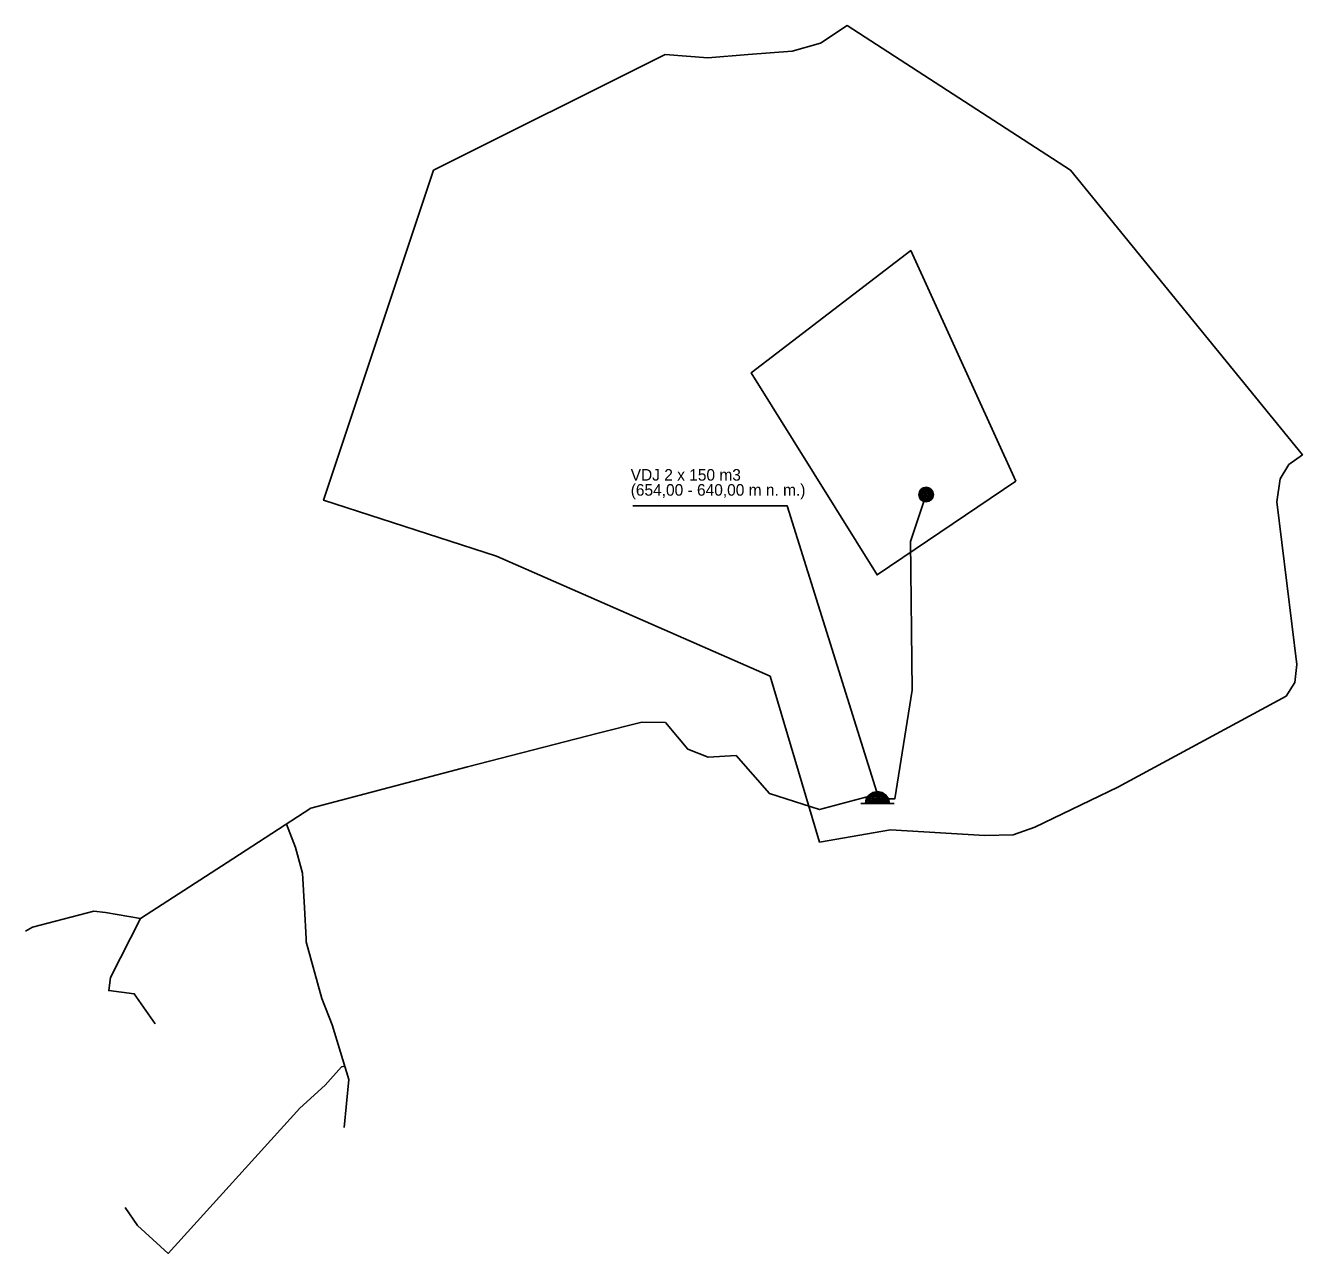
# Model space of a CAD drawing. Extents: x -547132 to -534149, y -1095664 to -1090118.
# Drawn here: x -542568 to -541466, y -1093042 to -1091982 of the extents above; entities that cross this region are included whole.
import ezdxf

# ---------------------------------------------------------------- set-up
doc = ezdxf.new("R2010")
doc.units = 0
for name, color, linetype in [('Vrstva 15', 7, 'Continuous'), ('Vrstva 3', 7, 'Continuous'), ('Vrstva 55', 7, 'Continuous'), ('Vrstva 56', 7, 'Continuous'), ('Vrstva 7', 7, 'Continuous')]:
    doc.layers.add(name, color=color, linetype=linetype)

msp = doc.modelspace()

# ---------------------------------------------------------------- linework, layer by layer
at = {"layer": 'Vrstva 15'}
for p, q in [((-541847.2, -1092653.9), (-541843.2, -1092653.9)), ((-541818.3, -1092653.9), (-541822.3, -1092653.9))]:
    msp.add_line(p, q, dxfattribs=at)
msp.add_lwpolyline([(-542043.9, -1092396.7), (-541910.8, -1092396.7), (-541831.8, -1092648.6)], dxfattribs=at)
for points in [[(-541843.2, -1092653.9), (-541842.4, -1092649.9), (-541840.1, -1092646.5), (-541836.7, -1092644.2), (-541832.8, -1092643.4), (-541828.8, -1092644.2), (-541825.4, -1092646.5), (-541823.1, -1092649.9), (-541822.3, -1092653.9)], [(-541842, -1092652.9), (-541841.5, -1092650.3), (-541839.4, -1092647.2), (-541836.4, -1092645.2), (-541832.8, -1092644.4), (-541829.1, -1092645.2), (-541826.1, -1092647.2), (-541824, -1092650.3), (-541823.5, -1092652.9)], [(-541840.8, -1092651.9), (-541840.5, -1092650.7), (-541838.7, -1092647.9), (-541836, -1092646.1), (-541832.8, -1092645.5), (-541829.5, -1092646.1), (-541826.8, -1092647.9), (-541825, -1092650.7), (-541824.7, -1092651.9)], [(-541839.5, -1092650.9), (-541838, -1092648.7), (-541835.6, -1092647.1), (-541832.8, -1092646.5), (-541829.9, -1092647.1), (-541827.5, -1092648.7), (-541826, -1092650.9)], [(-541837.6, -1092649.9), (-541837.3, -1092649.4), (-541835.2, -1092648), (-541832.8, -1092647.5), (-541830.3, -1092648), (-541828.2, -1092649.4), (-541827.9, -1092649.9)], [(-541834.5, -1092648.9), (-541832.8, -1092648.5), (-541831, -1092648.9)]]:
    msp.add_lwpolyline(points, close=True, dxfattribs=at)
at = {"layer": 'Vrstva 3'}
for points in [[(-541826.7, -1092649.7), (-541817.7, -1092649.7), (-541802.9, -1092555.9), (-541804.2, -1092427.5), (-541790.7, -1092387)], [(-542568.4, -1092764), (-542562.3, -1092760.5), (-542509.3, -1092746.7), (-542499.4, -1092748), (-542469.1, -1092753.1), (-542389.5, -1092701.6), (-542322.1, -1092658), (-542186.8, -1092622.2), (-542074, -1092593.1), (-542036.1, -1092583.7), (-542015.9, -1092583.8), (-541996.5, -1092607), (-541979, -1092613.9), (-541954.8, -1092612.5), (-541926, -1092645.1), (-541882.8, -1092659.1), (-541831.1, -1092645.1)], [(-542343, -1092671.6), (-542335.4, -1092691.7), (-542329.2, -1092714.1), (-542327.6, -1092743.7), (-542326.2, -1092770.6), (-542326, -1092773.4), (-542312.5, -1092822.2), (-542303.7, -1092845.1), (-542289.1, -1092892.1), (-542293.3, -1092933.7)], [(-542469.1, -1092753.1), (-542494.9, -1092804.2), (-542496.5, -1092815.4), (-542474.5, -1092818.2), (-542456.5, -1092844.2)], [(-542482.3, -1093002.6), (-542471.8, -1093018.3), (-542445.1, -1093042.4), (-542331.6, -1092916.9), (-542309.6, -1092897), (-542295.5, -1092881.2), (-542292.7, -1092880.6)]]:
    msp.add_lwpolyline(points, dxfattribs=at)
at = {"layer": 'Vrstva 55'}
msp.add_lwpolyline([(-541713.1, -1092375.5), (-541804, -1092176.3), (-541941.8, -1092282), (-541833.1, -1092456.4)], close=True, dxfattribs=at)
at = {"layer": 'Vrstva 56'}
msp.add_lwpolyline([(-541666, -1092107), (-541859, -1091982), (-541881.9, -1091997.2), (-541906.4, -1092004.2), (-541944.3, -1092007.1), (-541979.2, -1092010), (-542016, -1092007), (-542216, -1092107), (-542311, -1092392), (-542161.7, -1092440.3), (-541925.4, -1092543.9), (-541882.7, -1092687.2), (-541821.5, -1092676.7), (-541740, -1092681.4), (-541715.5, -1092680.8), (-541696.8, -1092674.4), (-541625.3, -1092639.6), (-541479.7, -1092561), (-541472.2, -1092549.3), (-541470.5, -1092533.8), (-541487.9, -1092393.3), (-541485, -1092373.5), (-541477.4, -1092361.2), (-541465.7, -1092352.6)], close=True, dxfattribs=at)
at = {"layer": 'Vrstva 7'}
for radius in [6.3, 5.3, 4.3, 3.3, 2.3, 1.3, 0.3]:
    msp.add_circle((-541790.7, -1092387), radius, dxfattribs=at)

# ---------------------------------------------------------------- texts
at = {"layer": 'Vrstva 15'}
for s, p in [('VDJ 2 x 150 m3', (-542045.8, -1092375)), ('(654,00 - 640,00 m n. m.)', (-542045.8, -1092388))]:
    msp.add_text(s, height=10, dxfattribs=at).set_placement(p)

doc.saveas('drawing.dxf')
